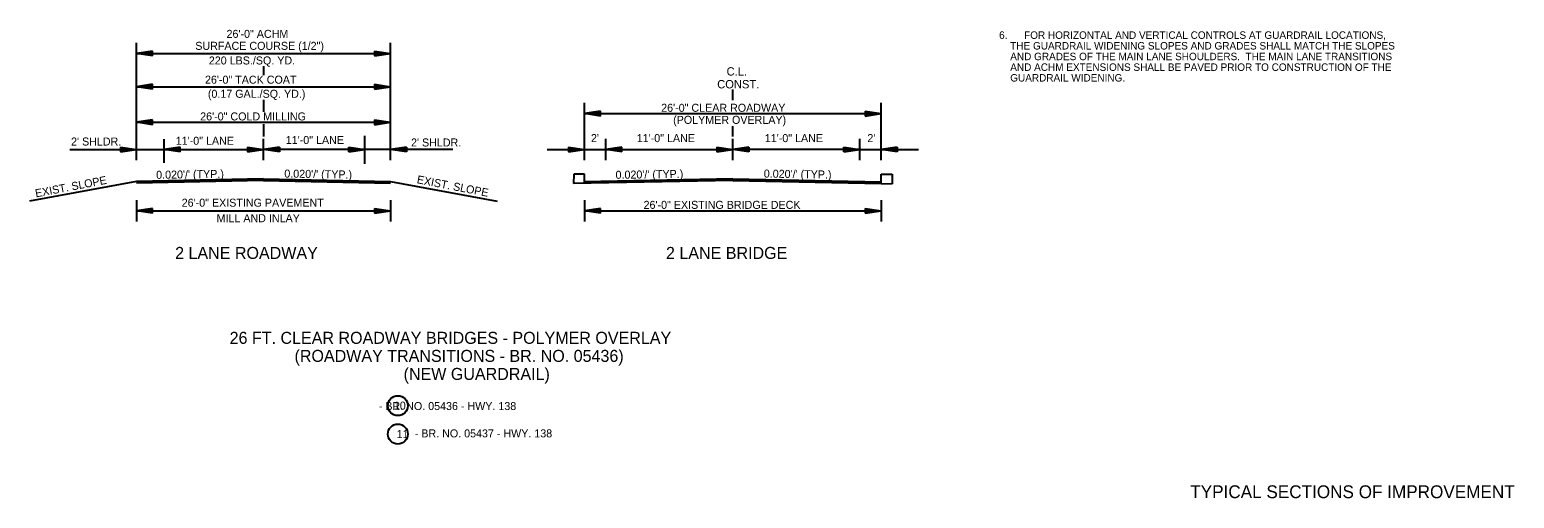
# Model space of a CAD drawing. Extents: x 545241 to 1930787, y -1971772 to 596640.
# Drawn here: x 546877 to 548268, y -1952272 to -1951833 of the extents above; entities that cross this region are included whole.
import ezdxf

# ---------------------------------------------------------------- set-up
doc = ezdxf.new("R2010")
doc.units = 0
for name, color, linetype in [('R_Border', 7, 'Continuous'), ('R_Border Notes', 7, 'Continuous'), ('R_Draft', 7, 'Continuous')]:
    doc.layers.add(name, color=color, linetype=linetype)

msp = doc.modelspace()

# ---------------------------------------------------------------- linework, layer by layer
at = {"layer": 'R_Border'}
for p, q in [((547386.4, -1951968.2), (547386.3, -1951977.2)), ((547396.5, -1951968.2), (547386.4, -1951968.2)), ((547396.5, -1951977), (547396.5, -1951968.2)), ((547674.5, -1951977), (547674.5, -1951968.2)), ((547674.5, -1951968.2), (547684.7, -1951968.2)), ((547684.7, -1951968.2), (547684.7, -1951977.4))]:
    msp.add_line(p, q, dxfattribs=at)
for centre in [(547221.6, -1952185.1), (547221.6, -1952211.7)]:
    msp.add_circle(centre, 9.34, dxfattribs=at)
at = {"layer": 'R_Draft'}
for p, q in [((546976.6, -1951955.2), (546976.6, -1951845.3)), ((547214.6, -1951955.2), (547214.6, -1951845.3)), ((546991.6, -1951853.1), (546976.6, -1951855.3)), ((546991.6, -1951857.6), (546976.6, -1951855.3)), ((546976.6, -1951855.3), (547214.6, -1951855.3)), ((546991.6, -1951853.4), (546979.1, -1951855.3)), ((546991.6, -1951857.2), (546979.1, -1951855.3)), ((546991.6, -1951853.8), (546981.7, -1951855.3)), ((546991.6, -1951856.8), (546981.7, -1951855.3)), ((546991.6, -1951854.2), (546984.2, -1951855.3)), ((546991.6, -1951856.4), (546984.2, -1951855.3)), ((546991.6, -1951854.6), (546986.7, -1951855.3)), ((546991.6, -1951856.1), (546986.7, -1951855.3)), ((546991.6, -1951855), (546989.2, -1951855.3)), ((546991.6, -1951855.7), (546989.2, -1951855.3)), ((546991.6, -1951857.6), (546991.6, -1951853.1)), ((547199.6, -1951853.1), (547214.6, -1951855.3)), ((547199.6, -1951853.1), (547199.6, -1951857.6)), ((547199.6, -1951853.4), (547212.1, -1951855.3)), ((547199.6, -1951853.8), (547209.5, -1951855.3)), ((547199.6, -1951854.2), (547207, -1951855.3)), ((547199.6, -1951854.6), (547204.5, -1951855.3)), ((547199.6, -1951855), (547202, -1951855.3)), ((547199.6, -1951857.6), (547214.6, -1951855.3)), ((547199.6, -1951856.1), (547204.5, -1951855.3)), ((547199.6, -1951856.8), (547209.5, -1951855.3)), ((547199.6, -1951857.2), (547212.1, -1951855.3)), ((547199.6, -1951856.4), (547207, -1951855.3)), ((547199.6, -1951855.7), (547202, -1951855.3)), ((547095.6, -1951867.3), (547095.6, -1951875.5)), ((546991.6, -1951884.1), (546976.6, -1951886.4)), ((546991.6, -1951888.6), (546976.6, -1951886.4)), ((546976.6, -1951886.4), (547214.6, -1951886.4)), ((546991.6, -1951884.5), (546979.1, -1951886.4)), ((546991.6, -1951888.2), (546979.1, -1951886.4)), ((546991.6, -1951884.9), (546981.7, -1951886.4)), ((546991.6, -1951887.9), (546981.7, -1951886.4)), ((546991.6, -1951885.3), (546984.2, -1951886.4)), ((546991.6, -1951887.5), (546984.2, -1951886.4)), ((546991.6, -1951885.6), (546986.7, -1951886.4)), ((546991.6, -1951887.1), (546986.7, -1951886.4)), ((546991.6, -1951886), (546989.2, -1951886.4)), ((546991.6, -1951886.7), (546989.2, -1951886.4)), ((546991.6, -1951888.6), (546991.6, -1951884.1)), ((547199.6, -1951884.1), (547214.6, -1951886.4)), ((547199.6, -1951884.1), (547199.6, -1951888.6)), ((547199.6, -1951884.5), (547212.1, -1951886.4)), ((547199.6, -1951884.9), (547209.5, -1951886.4)), ((547199.6, -1951885.3), (547207, -1951886.4)), ((547199.6, -1951885.6), (547204.5, -1951886.4)), ((547199.6, -1951886), (547202, -1951886.4)), ((547199.6, -1951888.6), (547214.6, -1951886.4)), ((547199.6, -1951887.1), (547204.5, -1951886.4)), ((547199.6, -1951887.9), (547209.5, -1951886.4)), ((547199.6, -1951888.2), (547212.1, -1951886.4)), ((547199.6, -1951887.5), (547207, -1951886.4)), ((547199.6, -1951886.7), (547202, -1951886.4)), ((547535.5, -1951898.9), (547535.5, -1951888.9)), ((547095.6, -1951898.6), (547095.6, -1951909.8)), ((547396.5, -1951955.2), (547396.5, -1951901.6)), ((547674.5, -1951955.2), (547674.5, -1951901.6)), ((546991.6, -1951917.5), (546976.6, -1951919.7)), ((546976.6, -1951919.7), (547214.6, -1951919.7)), ((546991.6, -1951922), (546976.6, -1951919.7)), ((546991.6, -1951917.9), (546979.1, -1951919.7)), ((546991.6, -1951921.6), (546979.1, -1951919.7)), ((546991.6, -1951918.2), (546981.7, -1951919.7)), ((546991.6, -1951921.2), (546981.7, -1951919.7)), ((546991.6, -1951918.6), (546984.2, -1951919.7)), ((546991.6, -1951920.9), (546984.2, -1951919.7)), ((546991.6, -1951919), (546986.7, -1951919.7)), ((546991.6, -1951920.5), (546986.7, -1951919.7)), ((546991.6, -1951919.4), (546989.2, -1951919.7)), ((546991.6, -1951920.1), (546989.2, -1951919.7)), ((546991.6, -1951922), (546991.6, -1951917.5)), ((547095.6, -1951914.9), (547095.6, -1951914.9)), ((547095.6, -1951921.4), (547095.6, -1951932.9)), ((547199.6, -1951917.5), (547214.6, -1951919.7)), ((547199.6, -1951917.5), (547199.6, -1951922)), ((547199.6, -1951917.9), (547212.1, -1951919.7)), ((547199.6, -1951918.2), (547209.5, -1951919.7)), ((547199.6, -1951918.6), (547207, -1951919.7)), ((547199.6, -1951919), (547204.5, -1951919.7)), ((547199.6, -1951919.4), (547202, -1951919.7)), ((547199.6, -1951922), (547214.6, -1951919.7)), ((547199.6, -1951920.5), (547204.5, -1951919.7)), ((547199.6, -1951921.2), (547209.5, -1951919.7)), ((547199.6, -1951921.6), (547212.1, -1951919.7)), ((547199.6, -1951920.9), (547207, -1951919.7)), ((547199.6, -1951920.1), (547202, -1951919.7)), ((547411.5, -1951909.4), (547396.5, -1951911.6)), ((547411.5, -1951913.9), (547396.5, -1951911.6)), ((547397.5, -1951911.6), (547673.5, -1951911.6)), ((547411.5, -1951909.7), (547399, -1951911.6)), ((547411.5, -1951913.5), (547399, -1951911.6)), ((547411.5, -1951910.1), (547401.6, -1951911.6)), ((547411.5, -1951913.1), (547401.6, -1951911.6)), ((547411.5, -1951910.5), (547404.1, -1951911.6)), ((547411.5, -1951912.7), (547404.1, -1951911.6)), ((547411.5, -1951910.9), (547406.6, -1951911.6)), ((547411.5, -1951912.3), (547406.6, -1951911.6)), ((547411.5, -1951911.3), (547409.1, -1951911.6)), ((547411.5, -1951912), (547409.1, -1951911.6)), ((547411.5, -1951913.9), (547411.5, -1951909.4)), ((547659.5, -1951909.4), (547674.5, -1951911.6)), ((547659.5, -1951909.4), (547659.5, -1951913.9)), ((547659.5, -1951909.7), (547672, -1951911.6)), ((547659.5, -1951910.1), (547669.4, -1951911.6)), ((547659.5, -1951910.5), (547666.9, -1951911.6)), ((547659.5, -1951910.9), (547664.4, -1951911.6)), ((547659.5, -1951911.3), (547661.9, -1951911.6)), ((547659.5, -1951913.9), (547674.5, -1951911.6)), ((547659.5, -1951912.3), (547664.4, -1951911.6)), ((547659.5, -1951913.1), (547669.4, -1951911.6)), ((547659.5, -1951913.5), (547672, -1951911.6)), ((547659.5, -1951912.7), (547666.9, -1951911.6)), ((547659.5, -1951912), (547661.9, -1951911.6)), ((547002.6, -1951957.6), (547002.6, -1951935.4)), ((547095.6, -1951955.2), (547095.6, -1951935.3)), ((547190.7, -1951958.6), (547190.7, -1951932.4)), ((547416.5, -1951955.2), (547416.5, -1951935.3)), ((547535.5, -1951933.1), (547535.5, -1951923.3)), ((547535.5, -1951955.2), (547535.5, -1951935.3)), ((547654.5, -1951955.2), (547654.5, -1951935.3)), ((546914.4, -1951945.2), (547095.6, -1951945.2)), ((546961.6, -1951942.9), (546976.6, -1951945.1)), ((546961.6, -1951942.9), (546961.6, -1951947.4)), ((546961.6, -1951943.3), (546974.1, -1951945.1)), ((546961.6, -1951943.6), (546971.5, -1951945.1)), ((546961.6, -1951944), (546969, -1951945.1)), ((546961.6, -1951944.4), (546966.5, -1951945.1)), ((546961.6, -1951944.8), (546964, -1951945.1)), ((546961.6, -1951947.4), (546976.6, -1951945.1)), ((546961.6, -1951945.9), (546966.5, -1951945.1)), ((546961.6, -1951946.6), (546971.5, -1951945.1)), ((546961.6, -1951947), (546974.1, -1951945.1)), ((546961.6, -1951946.3), (546969, -1951945.1)), ((546961.6, -1951945.5), (546964, -1951945.1)), ((547017.6, -1951942.9), (547002.6, -1951945.2)), ((547017.6, -1951947.4), (547002.6, -1951945.2)), ((547017.6, -1951943.3), (547005.1, -1951945.2)), ((547017.6, -1951947), (547005.1, -1951945.2)), ((547017.6, -1951943.7), (547007.7, -1951945.2)), ((547017.6, -1951946.7), (547007.7, -1951945.2)), ((547017.6, -1951944.1), (547010.2, -1951945.2)), ((547017.6, -1951946.3), (547010.2, -1951945.2)), ((547017.6, -1951944.4), (547012.7, -1951945.2)), ((547017.6, -1951945.9), (547012.7, -1951945.2)), ((547017.6, -1951944.8), (547015.2, -1951945.2)), ((547017.6, -1951945.5), (547015.2, -1951945.2)), ((547017.6, -1951947.4), (547017.6, -1951942.9)), ((547080.6, -1951942.9), (547095.6, -1951945.2)), ((547080.6, -1951942.9), (547080.6, -1951947.4)), ((547080.6, -1951943.3), (547093.1, -1951945.2)), ((547080.6, -1951943.7), (547090.5, -1951945.2)), ((547080.6, -1951944), (547088, -1951945.2)), ((547080.6, -1951944.4), (547085.5, -1951945.2)), ((547080.6, -1951944.8), (547083, -1951945.2)), ((547080.6, -1951947.4), (547095.6, -1951945.2)), ((547080.6, -1951945.9), (547085.5, -1951945.2)), ((547080.6, -1951946.6), (547090.5, -1951945.2)), ((547080.6, -1951947), (547093.1, -1951945.2)), ((547080.6, -1951946.3), (547088, -1951945.2)), ((547080.6, -1951945.5), (547083, -1951945.2)), ((547110.6, -1951942.9), (547095.6, -1951945.2)), ((547273, -1951945.2), (547095.6, -1951945.2)), ((547110.6, -1951947.4), (547095.6, -1951945.2)), ((547110.6, -1951943.3), (547098.1, -1951945.2)), ((547110.6, -1951947), (547098.1, -1951945.2)), ((547110.6, -1951943.7), (547100.7, -1951945.2)), ((547110.6, -1951946.6), (547100.7, -1951945.2)), ((547110.6, -1951944), (547103.2, -1951945.2)), ((547110.6, -1951946.3), (547103.2, -1951945.2)), ((547110.6, -1951944.4), (547105.7, -1951945.2)), ((547110.6, -1951945.9), (547105.7, -1951945.2)), ((547110.6, -1951944.8), (547108.2, -1951945.2)), ((547110.6, -1951945.5), (547108.2, -1951945.2)), ((547110.6, -1951942.9), (547110.6, -1951947.4)), ((547175.7, -1951942.9), (547190.7, -1951945.1)), ((547175.7, -1951947.4), (547175.7, -1951942.9)), ((547175.7, -1951943.3), (547188.2, -1951945.1)), ((547175.7, -1951943.7), (547185.6, -1951945.1)), ((547175.7, -1951944), (547183.1, -1951945.1)), ((547175.7, -1951944.4), (547180.6, -1951945.1)), ((547175.7, -1951944.8), (547178.1, -1951945.1)), ((547175.7, -1951947.4), (547190.7, -1951945.1)), ((547175.7, -1951945.9), (547180.6, -1951945.1)), ((547175.7, -1951946.6), (547185.6, -1951945.1)), ((547175.7, -1951947), (547188.2, -1951945.1)), ((547175.7, -1951946.3), (547183.1, -1951945.1)), ((547175.7, -1951945.5), (547178.1, -1951945.1)), ((547229.7, -1951942.9), (547214.7, -1951945.1)), ((547229.7, -1951947.4), (547214.7, -1951945.1)), ((547229.7, -1951943.3), (547217.2, -1951945.1)), ((547229.7, -1951947), (547217.2, -1951945.1)), ((547229.7, -1951943.7), (547219.8, -1951945.1)), ((547229.7, -1951946.6), (547219.8, -1951945.1)), ((547229.7, -1951944), (547222.3, -1951945.1)), ((547229.7, -1951946.3), (547222.3, -1951945.1)), ((547229.7, -1951944.4), (547224.8, -1951945.1)), ((547229.7, -1951945.9), (547224.8, -1951945.1)), ((547229.7, -1951944.8), (547227.3, -1951945.1)), ((547229.7, -1951945.5), (547227.3, -1951945.1)), ((547229.7, -1951942.9), (547229.7, -1951947.4)), ((547361.5, -1951945.2), (547535.5, -1951945.2)), ((547381.5, -1951942.9), (547396.5, -1951945.2)), ((547381.5, -1951942.9), (547381.5, -1951947.4)), ((547381.5, -1951943.3), (547394, -1951945.2)), ((547381.5, -1951943.7), (547391.4, -1951945.2)), ((547381.5, -1951944), (547388.9, -1951945.2)), ((547381.5, -1951944.4), (547386.4, -1951945.2)), ((547381.5, -1951944.8), (547383.9, -1951945.2)), ((547381.5, -1951947.4), (547396.5, -1951945.2)), ((547381.5, -1951945.9), (547386.4, -1951945.2)), ((547381.5, -1951946.6), (547391.4, -1951945.2)), ((547381.5, -1951947), (547394, -1951945.2)), ((547381.5, -1951946.3), (547388.9, -1951945.2)), ((547381.5, -1951945.5), (547383.9, -1951945.2)), ((547431.5, -1951942.9), (547416.5, -1951945.2)), ((547431.5, -1951947.4), (547416.5, -1951945.2)), ((547431.5, -1951943.3), (547419, -1951945.2)), ((547431.5, -1951947), (547419, -1951945.2)), ((547431.5, -1951943.7), (547421.6, -1951945.2)), ((547431.5, -1951946.6), (547421.6, -1951945.2)), ((547431.5, -1951944), (547424.1, -1951945.2)), ((547431.5, -1951946.3), (547424.1, -1951945.2)), ((547431.5, -1951944.4), (547426.6, -1951945.2)), ((547431.5, -1951945.9), (547426.6, -1951945.2)), ((547431.5, -1951944.8), (547429.1, -1951945.2)), ((547431.5, -1951945.5), (547429.1, -1951945.2)), ((547431.5, -1951947.4), (547431.5, -1951942.9)), ((547520.5, -1951942.9), (547535.5, -1951945.2)), ((547520.5, -1951942.9), (547520.5, -1951947.4)), ((547520.5, -1951943.3), (547533, -1951945.2)), ((547520.5, -1951943.7), (547530.4, -1951945.2)), ((547520.5, -1951944), (547527.9, -1951945.2)), ((547520.5, -1951944.4), (547525.4, -1951945.2)), ((547520.5, -1951944.8), (547522.9, -1951945.2)), ((547520.5, -1951947.4), (547535.5, -1951945.2)), ((547520.5, -1951945.9), (547525.4, -1951945.2)), ((547520.5, -1951946.6), (547530.4, -1951945.2)), ((547520.5, -1951947), (547533, -1951945.2)), ((547520.5, -1951946.3), (547527.9, -1951945.2)), ((547520.5, -1951945.5), (547522.9, -1951945.2)), ((547550.5, -1951942.9), (547535.5, -1951945.2)), ((547655.5, -1951945.2), (547535.5, -1951945.2)), ((547550.5, -1951947.4), (547535.5, -1951945.2)), ((547550.5, -1951943.3), (547538, -1951945.2)), ((547550.5, -1951947), (547538, -1951945.2)), ((547550.5, -1951943.7), (547540.6, -1951945.2)), ((547550.5, -1951946.6), (547540.6, -1951945.2)), ((547550.5, -1951944), (547543.1, -1951945.2)), ((547550.5, -1951946.3), (547543.1, -1951945.2)), ((547550.5, -1951944.4), (547545.6, -1951945.2)), ((547550.5, -1951945.9), (547545.6, -1951945.2)), ((547550.5, -1951944.8), (547548.1, -1951945.2)), ((547550.5, -1951945.5), (547548.1, -1951945.2)), ((547550.5, -1951942.9), (547550.5, -1951947.4)), ((547639.5, -1951942.9), (547654.5, -1951945.2)), ((547639.5, -1951947.4), (547639.5, -1951942.9)), ((547639.5, -1951943.3), (547652, -1951945.2)), ((547639.5, -1951943.7), (547649.4, -1951945.2)), ((547639.5, -1951944), (547646.9, -1951945.2)), ((547639.5, -1951944.4), (547644.4, -1951945.2)), ((547639.5, -1951944.8), (547641.9, -1951945.2)), ((547639.5, -1951947.4), (547654.5, -1951945.2)), ((547639.5, -1951945.9), (547644.4, -1951945.2)), ((547639.5, -1951946.6), (547649.4, -1951945.2)), ((547639.5, -1951947), (547652, -1951945.2)), ((547639.5, -1951946.3), (547646.9, -1951945.2)), ((547639.5, -1951945.5), (547641.9, -1951945.2)), ((547655.5, -1951945.2), (547709.5, -1951945.2)), ((547689.5, -1951942.9), (547674.5, -1951945.2)), ((547689.5, -1951947.4), (547674.5, -1951945.2)), ((547689.5, -1951943.3), (547677, -1951945.2)), ((547689.5, -1951947), (547677, -1951945.2)), ((547689.5, -1951943.7), (547679.6, -1951945.2)), ((547689.5, -1951946.6), (547679.6, -1951945.2)), ((547689.5, -1951944), (547682.1, -1951945.2)), ((547689.5, -1951946.3), (547682.1, -1951945.2)), ((547689.5, -1951944.4), (547684.6, -1951945.2)), ((547689.5, -1951945.9), (547684.6, -1951945.2)), ((547689.5, -1951944.8), (547687.1, -1951945.2)), ((547689.5, -1951945.5), (547687.1, -1951945.2)), ((547689.5, -1951942.9), (547689.5, -1951947.4)), ((546976.6, -1951975.1), (546876.6, -1951993.7)), ((547095.6, -1951972.8), (546976.6, -1951975.1)), ((547095.6, -1951973.1), (546976.6, -1951975.4)), ((547095.6, -1951973.4), (546976.6, -1951975.7)), ((547095.6, -1951973.7), (546976.6, -1951976)), ((547095.6, -1951974), (546976.6, -1951976.3)), ((547095.6, -1951974.3), (546976.6, -1951976.6)), ((547095.6, -1951972.8), (547214.6, -1951975.1)), ((547095.6, -1951973.1), (547214.6, -1951975.4)), ((547095.6, -1951973.4), (547214.6, -1951975.7)), ((547095.6, -1951973.7), (547214.6, -1951976)), ((547095.6, -1951974), (547214.6, -1951976.3)), ((547095.6, -1951974.3), (547214.6, -1951976.6)), ((547214.6, -1951975.1), (547314.7, -1951993.5)), ((547535.5, -1951974.3), (547386.3, -1951977.2)), ((547535.5, -1951972.8), (547396.5, -1951975.5)), ((547535.5, -1951973.1), (547396.5, -1951975.8)), ((547535.5, -1951973.4), (547396.5, -1951976.1)), ((547535.5, -1951973.7), (547396.5, -1951976.4)), ((547535.5, -1951974), (547396.5, -1951976.7)), ((547535.5, -1951972.8), (547674.5, -1951975.5)), ((547535.5, -1951973.1), (547674.5, -1951975.8)), ((547535.5, -1951973.4), (547674.5, -1951976.1)), ((547535.5, -1951973.7), (547674.5, -1951976.4)), ((547535.5, -1951974), (547674.5, -1951976.7)), ((547535.5, -1951974.3), (547674.5, -1951977)), ((547674.5, -1951977.2), (547684.7, -1951977.4)), ((546976.6, -1951992.6), (546976.6, -1952012.6)), ((546991.6, -1952000.4), (546976.6, -1952002.6)), ((546991.6, -1952004.9), (546976.6, -1952002.6)), ((546977.6, -1952002.6), (547213.6, -1952002.6)), ((546991.6, -1952000.7), (546979.1, -1952002.6)), ((546991.6, -1952004.5), (546979.1, -1952002.6)), ((546991.6, -1952001.1), (546981.7, -1952002.6)), ((546991.6, -1952004.1), (546981.7, -1952002.6)), ((546991.6, -1952001.5), (546984.2, -1952002.6)), ((546991.6, -1952003.7), (546984.2, -1952002.6)), ((546991.6, -1952001.9), (546986.7, -1952002.6)), ((546991.6, -1952003.3), (546986.7, -1952002.6)), ((546991.6, -1952002.3), (546989.2, -1952002.6)), ((546991.6, -1952003), (546989.2, -1952002.6)), ((546991.6, -1952004.9), (546991.6, -1952000.4)), ((547199.6, -1952000.4), (547214.6, -1952002.6)), ((547199.6, -1952000.4), (547199.6, -1952004.9)), ((547199.6, -1952000.7), (547212.1, -1952002.6)), ((547199.6, -1952001.1), (547209.5, -1952002.6)), ((547199.6, -1952001.5), (547207, -1952002.6)), ((547199.6, -1952001.9), (547204.5, -1952002.6)), ((547199.6, -1952002.3), (547202, -1952002.6)), ((547199.6, -1952004.9), (547214.6, -1952002.6)), ((547199.6, -1952003.4), (547204.5, -1952002.6)), ((547199.6, -1952004.1), (547209.5, -1952002.6)), ((547199.6, -1952004.5), (547212.1, -1952002.6)), ((547199.6, -1952003.7), (547207, -1952002.6)), ((547199.6, -1952003), (547202, -1952002.6)), ((547214.6, -1951992.6), (547214.6, -1952012.6)), ((547396.5, -1951992.6), (547396.5, -1952012.6)), ((547411.5, -1952000.4), (547396.5, -1952002.6)), ((547411.5, -1952004.9), (547396.5, -1952002.6)), ((547397.5, -1952002.6), (547674.5, -1952002.6)), ((547411.5, -1952000.7), (547399, -1952002.6)), ((547411.5, -1952004.5), (547399, -1952002.6)), ((547411.5, -1952001.1), (547401.6, -1952002.6)), ((547411.5, -1952004.1), (547401.6, -1952002.6)), ((547411.5, -1952001.5), (547404.1, -1952002.6)), ((547411.5, -1952003.7), (547404.1, -1952002.6)), ((547411.5, -1952001.9), (547406.6, -1952002.6)), ((547411.5, -1952003.3), (547406.6, -1952002.6)), ((547411.5, -1952002.3), (547409.1, -1952002.6)), ((547411.5, -1952003), (547409.1, -1952002.6)), ((547411.5, -1952004.9), (547411.5, -1952000.4)), ((547659.5, -1952000.4), (547674.5, -1952002.6)), ((547659.5, -1952000.4), (547659.5, -1952004.9)), ((547659.5, -1952000.7), (547672, -1952002.6)), ((547659.5, -1952001.1), (547669.4, -1952002.6)), ((547659.5, -1952001.5), (547666.9, -1952002.6)), ((547659.5, -1952001.9), (547664.4, -1952002.6)), ((547659.5, -1952002.3), (547661.9, -1952002.6)), ((547659.5, -1952004.9), (547674.5, -1952002.6)), ((547659.5, -1952003.4), (547664.4, -1952002.6)), ((547659.5, -1952004.1), (547669.4, -1952002.6)), ((547659.5, -1952004.5), (547672, -1952002.6)), ((547659.5, -1952003.7), (547666.9, -1952002.6)), ((547659.5, -1952003), (547661.9, -1952002.6)), ((547674.5, -1951992.6), (547674.5, -1952012.6))]:
    msp.add_line(p, q, dxfattribs=at)

# ---------------------------------------------------------------- texts
at = {"layer": 'R_Border'}
msp.add_text('10', height=7.5, dxfattribs=at).set_placement((547217.9, -1952188.8))
msp.add_text('TYPICAL SECTIONS OF IMPROVEMENT', height=12, rotation=360, dxfattribs=at).set_placement((547964.2, -1952271.7))
at = {"layer": 'R_Border Notes'}
for s, p in [('6.      FOR HORIZONTAL AND VERTICAL CONTROLS AT GUARDRAIL LOCATIONS,', (547785.1, -1951841.6)), ('    THE GUARDRAIL WIDENING SLOPES AND GRADES SHALL MATCH THE SLOPES', (547785.1, -1951851.6)), ('    AND GRADES OF THE MAIN LANE SHOULDERS.  THE MAIN LANE TRANSITIONS', (547785.1, -1951861.6)), ('    AND ACHM EXTENSIONS SHALL BE PAVED PRIOR TO CONSTRUCTION OF THE', (547785.1, -1951871.6)), ('    GUARDRAIL WIDENING.', (547785.1, -1951881.6))]:
    msp.add_text(s, height=7, dxfattribs=at).set_placement(p)
at = {"layer": 'R_Draft'}
for s, height, p in [('26\'-0" ACHM ', 7.5, (547061.1, -1951840.7)), ('SURFACE COURSE (1/2")', 7.5, (547031.8, -1951851.9)), ('220 LBS./SQ. YD. ', 7.5, (547044.5, -1951865.6)), ('26\'-0" TACK COAT', 7.5, (547040.9, -1951883.6)), ('CONST.', 7.8, (547520.9, -1951888)), ('C.L.', 7.8, (547529.7, -1951876)), ('(0.17 GAL./SQ. YD.)', 7.5, (547043.6, -1951896.8)), ('26\'-0" CLEAR ROADWAY ', 7.5, (547468.4, -1951909.9)), ('26\'-0" COLD MILLING', 7.5, (547036.4, -1951918)), ('(POLYMER OVERLAY)', 7.5, (547479.6, -1951921.2)), ("2' SHLDR.", 7.5, (546915.4, -1951941.5)), ('11\'-0" LANE', 7.5, (547013.5, -1951940.8)), ('11\'-0" LANE', 7.5, (547116.6, -1951940.1)), ("2' SHLDR.", 7.5, (547234, -1951942.4)), ("2'", 7.5, (547402.6, -1951938.3)), ('11\'-0" LANE', 7.5, (547445.5, -1951938.3)), ('11\'-0" LANE', 7.5, (547565.5, -1951938.3)), ("2'", 7.5, (547661.6, -1951938.3)), ('26\'-0" EXISTING PAVEMENT ', 7.5, (547019.1, -1951998.8)), ('26\'-0" EXISTING BRIDGE DECK', 7.5, (547451.9, -1952000.8)), ('MILL AND INLAY', 7.5, (547051.8, -1952013.3)), ('2 LANE ROADWAY', 11.25, (547012.9, -1952047.7)), ('2 LANE BRIDGE', 11.25, (547472.9, -1952047.7)), ('26 FT. CLEAR ROADWAY BRIDGES - POLYMER OVERLAY', 11.25, (547064, -1952127.2)), ('(ROADWAY TRANSITIONS - BR. NO. 05436)', 11.25, (547124.8, -1952144.1)), ('(NEW GUARDRAIL)', 11.25, (547227, -1952161)), ('       - BR. NO. 05436 - HWY. 138 ', 7.5, (547184.3, -1952189.2)), ('11', 7.5, (547220.4, -1952215.5)), ('- BR. NO. 05437 - HWY. 138', 7.5, (547237.5, -1952214.8))]:
    msp.add_text(s, height=height, dxfattribs=at).set_placement(p)
for s, rotation, p in [('EXIST. SLOPE', 10.8829, (546882.5, -1951990.1)), ("0.020'/' (TYP.)", 0.8719, (546995.2, -1951972.7)), ("0.020'/' (TYP.)", 359.1281, (547115.2, -1951971.5)), ('EXIST. SLOPE', 349.1171, (547239, -1951976.7)), ("0.020'/' (TYP.)", 0.8719, (547425.7, -1951972.7)), ("0.020'/' (TYP.)", 359.1281, (547564.5, -1951971.5))]:
    msp.add_text(s, height=7.5, rotation=rotation, dxfattribs=at).set_placement(p)

doc.saveas('drawing.dxf')
